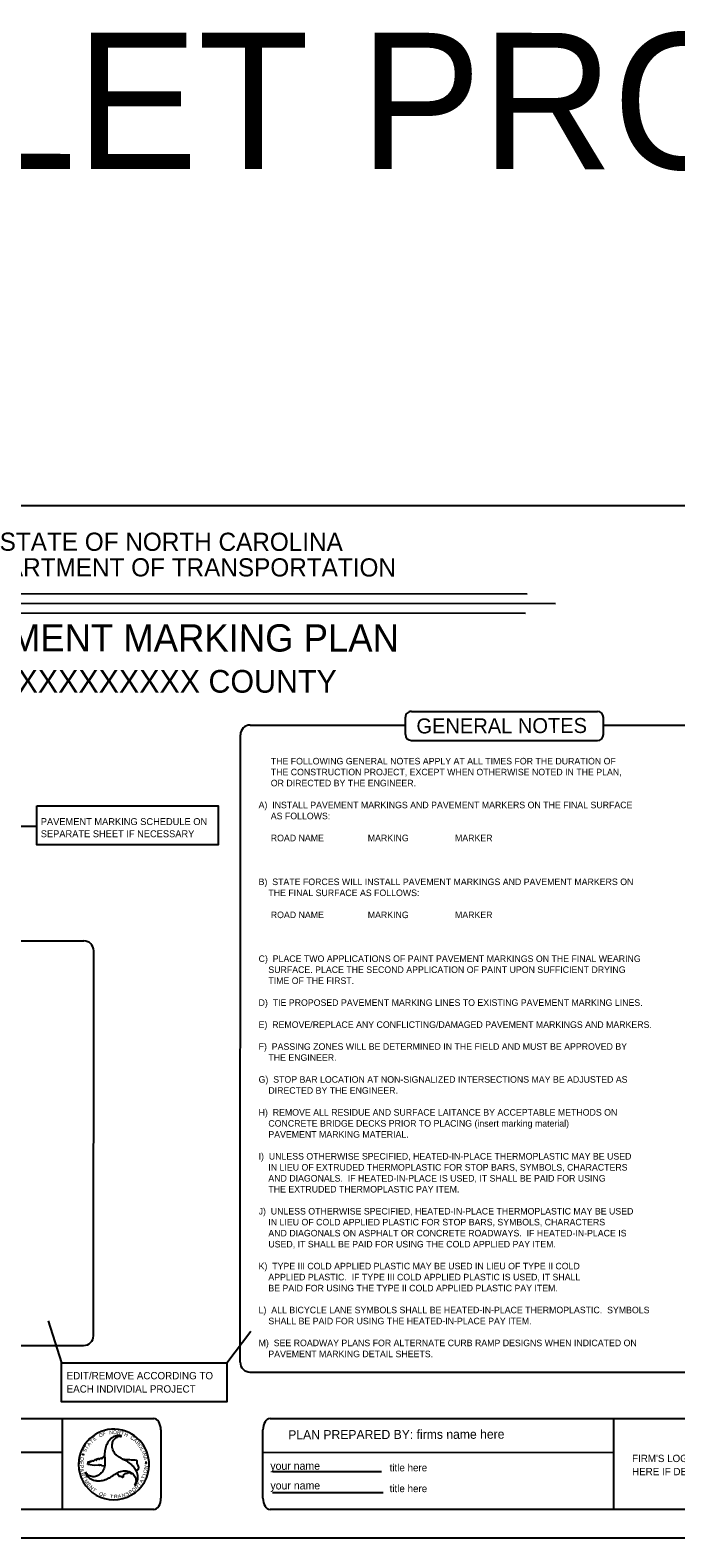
# Model space of a CAD drawing. Extents: x 2412958 to 2415566, y 564352 to 569392.
# Drawn here: x 2413907 to 2414563, y 567858 to 569392 of the extents above; entities that cross this region are included whole.
import ezdxf

# ---------------------------------------------------------------- set-up
doc = ezdxf.new("R2010")
doc.units = 0
for name, color, linetype in [('Default', 7, 'Continuous'), ('Sheet Title CELL', 7, 'Continuous'), ('Typical Detail Wedge1 CELL', 7, 'Continuous')]:
    doc.layers.add(name, color=color, linetype=linetype)

msp = doc.modelspace()

# ---------------------------------------------------------------- linework, layer by layer
at = {"layer": 'Default'}
for p, q in [((2413720.6, 568581.9), (2413913.3, 568581.9)), ((2413924.9, 568078.8), (2413938.3, 568036.1)), ((2414106.4, 568036.1), (2414130.9, 568068.2)), ((2413425.3, 567979.1), (2414032.2, 567979.2)), ((2413939.2, 567979.2), (2413939.2, 567886.8)), ((2414150.5, 567979.2), (2414647.4, 567979.2)), ((2414500.2, 567886.9), (2414500.2, 567979.2)), ((2414039.4, 567967.7), (2414039.5, 567898.4)), ((2414143.3, 567898.3), (2414143.3, 567967.7)), ((2413418.1, 567944.8), (2413939.2, 567945)), ((2414143.3, 567944.8), (2414500.2, 567945)), ((2414153.1, 567925.4), (2414263.8, 567925.4)), ((2414153.1, 567904.2), (2414265.6, 567904.2)), ((2414032.3, 567886.9), (2413425.3, 567886.8)), ((2414647.4, 567886.9), (2414150.5, 567886.8))]:
    msp.add_line(p, q, dxfattribs=at)
for points in [[(2413718.3, 568818.8), (2414412.1, 568818.4)], [(2413686.3, 568809), (2414440.8, 568808.7)], [(2413716.6, 568799.3), (2414410.4, 568798.9)]]:
    msp.add_lwpolyline(points, dxfattribs=at)
for points in [[(2413913.3, 568602.9), (2414097.7, 568602.9), (2414097.7, 568563.1), (2413913.3, 568563.1)], [(2413938.3, 568036.1), (2414106.4, 568036.1), (2414106.4, 567996.3), (2413938.3, 567996.3)]]:
    msp.add_lwpolyline(points, close=True, dxfattribs=at)
for centre, major_axis, start_param, end_param in [((2414032.2, 567967.7), (0, 11.5), 4.713091, 6.283887), ((2414150.5, 567967.7), (0, 11.5), 0.000702, 1.571498), ((2414032.3, 567898.4), (0, -11.5), 0.000702, 1.571498), ((2414150.5, 567898.3), (0, -11.5), 4.713091, 6.283887)]:
    msp.add_ellipse(centre, major_axis=major_axis, ratio=0.62659, start_param=start_param, end_param=end_param, dxfattribs=at)
at = {"layer": 'Sheet Title CELL'}
for p, q in [((2414288.2, 568675.3), (2414288.2, 568692.9)), ((2414489.6, 568675.2), (2414489.6, 568692.8)), ((2414130.3, 568685), (2414288.2, 568684.9)), ((2414489.6, 568684.9), (2414651.4, 568684.8)), ((2414120.1, 568036.6), (2414120.3, 568675)), ((2413885.3, 568465.4), (2413961.1, 568465.3)), ((2413970.9, 568063.4), (2413971.1, 568455.3)), ((2413428, 568053.6), (2413960.9, 568053.6)), ((2414130.1, 568026.6), (2414651.2, 568026.4)), ((2413999.5, 567961.5), (2413999.4, 567961.4)), ((2413999.5, 567961.5), (2413999.4, 567961.4)), ((2413960, 567942.6), (2413959.6, 567943)), ((2413959.6, 567943), (2413960.2, 567943)), ((2413959.8, 567942), (2413960, 567942.6)), ((2413960.3, 567942.3), (2413959.8, 567942)), ((2413960.2, 567943), (2413960.5, 567943.5)), ((2413960.8, 567941.9), (2413960.3, 567942.3)), ((2413960.5, 567943.5), (2413960.6, 567942.9)), ((2413960.6, 567942.9), (2413961.2, 567942.8)), ((2413961.2, 567942.8), (2413960.7, 567942.5)), ((2413960.7, 567942.5), (2413960.8, 567941.9)), ((2413965, 567932.6), (2413965.4, 567934.8)), ((2413972, 567931.4), (2413965, 567932.6)), ((2413976.2, 567932), (2413972, 567931.4)), ((2413982.2, 567930.7), (2413979.2, 567931.2)), ((2414000.4, 567938.2), (2414000.4, 567938.2)), ((2414024.2, 567934.7), (2414023.5, 567934.7)), ((2414023.5, 567934.7), (2414024, 567934.3)), ((2414024, 567934.3), (2414023.8, 567933.7)), ((2414023.8, 567933.7), (2414024.3, 567934)), ((2414024.5, 567935.2), (2414024.2, 567934.7)), ((2414024.3, 567934), (2414024.8, 567933.6)), ((2414024.6, 567934.6), (2414024.5, 567935.2)), ((2414025.2, 567934.5), (2414024.6, 567934.6)), ((2414024.7, 567934.2), (2414025.2, 567934.5)), ((2414024.8, 567933.6), (2414024.7, 567934.2)), ((2413997.4, 567919.9), (2413994.8, 567923.7)), ((2413994.8, 567923.7), (2413994.8, 567923.7))]:
    msp.add_line(p, q, dxfattribs=at)
msp.add_lwpolyline([(2414775.5, 568908), (2413275.5, 568907.9), (2413275.6, 567857.9), (2414775.6, 567858)], close=True, dxfattribs=at)
for points in [[(2414294.2, 568698.9), (2414483.6, 568698.8)], [(2414294.2, 568669.3), (2414483.6, 568669.2)]]:
    msp.add_lwpolyline(points, dxfattribs=at)
for centre, radius, start, end in [((2414294.2, 568692.9), 6, 89.9734, 179.9734), ((2414483.6, 568692.8), 6, 359.9734, 89.9734), ((2414130.3, 568675), 10, 89.9734, 179.9734), ((2414294.2, 568675.3), 6, 179.9734, 269.9734), ((2414483.6, 568675.2), 6, 269.9734, 359.9734), ((2413961.1, 568455.3), 10, 359.9734, 89.9734), ((2413960.9, 568063.6), 10, 269.9734, 359.9734), ((2414130.1, 568036.6), 10, 179.9734, 269.9734), ((2413991.6, 567932.6), 35.9, 352.4211, 172.4211), ((2414022.6, 568134.3), 197.4, 258.0996, 258.1992), ((2413991.6, 567932.6), 35.9, 172.4211, 352.4211), ((2414022.6, 568134.3), 197.4, 263.5387, 267.7447)]:
    msp.add_arc(centre, radius, start, end, dxfattribs=at)
for points in [[(2413999.4, 567961.4), (2413998.6, 567961.7), (2413996.1, 567962), (2413993.5, 567961.5), (2413993.3, 567961.4), (2413991.9, 567960.9), (2413990.5, 567960.1), (2413988.2, 567958.5), (2413986.3, 567956.3), (2413985.6, 567955.4), (2413985, 567954.2), (2413983.8, 567951.7), (2413983, 567949.3), (2413982.5, 567946.3), (2413982.2, 567943.7), (2413982.2, 567941), (2413982.4, 567938.3), (2413982.4, 567935.6), (2413982.4, 567932.9), (2413982.1, 567930.3), (2413982, 567930), (2413981.2, 567927.3), (2413979.7, 567924.9), (2413977.9, 567923.1), (2413976.9, 567922.2), (2413975.6, 567921.4), (2413974.8, 567920.9), (2413973, 567920.3), (2413970.4, 567920.1), (2413967.9, 567920.5), (2413965.8, 567921.4), (2413964, 567922.9), (2413962.7, 567924.9)], [(2414012.7, 567911.4), (2414013.4, 567911.9), (2414014.8, 567913.9), (2414015.7, 567916.4), (2414015.8, 567916.7), (2414016, 567918.1), (2414016.1, 567919.8), (2414015.8, 567922.6), (2414014.8, 567925.2), (2414014.4, 567926.3), (2414013.7, 567927.5), (2414012.1, 567929.7), (2414010.4, 567931.6), (2414008.1, 567933.6), (2414006, 567935.1), (2414003.6, 567936.5), (2414001.2, 567937.7), (2413998.9, 567939), (2413996.5, 567940.4), (2413994.4, 567942), (2413994.2, 567942.1), (2413992.2, 567944.3), (2413991, 567946.7), (2413990.2, 567949.2), (2413990, 567950.4), (2413990, 567952), (2413990, 567952.9), (2413990.3, 567954.8), (2413991.4, 567957.2), (2413993, 567959.1), (2413994.9, 567960.5), (2413997.1, 567961.3), (2413999.4, 567961.4), (2413999.5, 567961.5)], [(2413965.4, 567934.8), (2413965.3, 567935), (2413965.7, 567935.2), (2413966.7, 567934.7), (2413967.3, 567935), (2413967.3, 567935.5), (2413967.8, 567935.9), (2413968.5, 567935.6), (2413969.3, 567936.4), (2413969.9, 567936.4), (2413971.1, 567936.3), (2413972.8, 567937.6), (2413973.5, 567937.6), (2413973.6, 567937.2), (2413973.9, 567937), (2413974.7, 567938.2), (2413974.9, 567938.3), (2413976.2, 567938.6), (2413976.4, 567938.4), (2413976.5, 567937.8), (2413976.6, 567937.7), (2413977, 567937.9), (2413977.6, 567938.5), (2413978.7, 567938.9), (2413979.7, 567938.6), (2413980, 567939.5), (2413981.4, 567940.2), (2413981.8, 567940.6), (2413981.9, 567941.2)], [(2413982.2, 567941.1), (2413982.2, 567941), (2413982.4, 567938.3), (2413982.4, 567935.6), (2413982.4, 567932.9), (2413982.2, 567930.7)], [(2413962.7, 567924.9), (2413962.9, 567924), (2413963.9, 567921.7), (2413965.6, 567919.7), (2413965.8, 567919.6), (2413966.9, 567918.6), (2413968.3, 567917.8), (2413970.9, 567916.6), (2413973.7, 567916.1), (2413974.8, 567915.9), (2413976.2, 567915.9), (2413978.9, 567916.2), (2413981.4, 567916.7), (2413984.3, 567917.7), (2413986.6, 567918.8), (2413989, 567920.2), (2413991.3, 567921.7), (2413993.6, 567923), (2413995.9, 567924.4), (2413998.4, 567925.4), (2413998.7, 567925.5), (2414001.5, 567926.1), (2414004.2, 567926), (2414006.7, 567925.5), (2414007.9, 567925), (2414009.3, 567924.2), (2414010.1, 567923.8), (2414011.5, 567922.5), (2414013.1, 567920.4), (2414013.9, 567918.1), (2414014.2, 567915.8), (2414013.8, 567913.5), (2414012.7, 567911.4)], [(2413979.2, 567931.2), (2413979, 567931.7), (2413978.5, 567932), (2413977.7, 567931.7), (2413977.1, 567931.8), (2413976.5, 567932.3), (2413976.2, 567932)], [(2413994.8, 567923.7), (2413995.9, 567924.4), (2413998.4, 567925.4), (2413998.7, 567925.5), (2414001.5, 567926.1), (2414004.2, 567926), (2414006.7, 567925.5), (2414007.9, 567925), (2414009.3, 567924.2), (2414010.1, 567923.8)], [(2414010.1, 567923.8), (2414009.6, 567923.2), (2414009.1, 567923.2), (2414008.2, 567924.1), (2414007, 567924.1), (2414006.4, 567924.5), (2414006.1, 567924.5), (2414005.1, 567923.5), (2414003.8, 567923.4), (2414001.7, 567922.3), (2414001.2, 567921.5), (2414001.1, 567919.7), (2414000.6, 567919.4), (2414000, 567919.6), (2413998.9, 567920.2), (2413997.4, 567919.9)], [(2414014.2, 567926.8), (2414013.7, 567927.5), (2414012.1, 567929.7), (2414010.4, 567931.6), (2414008.1, 567933.6), (2414006, 567935.1), (2414003.6, 567936.5), (2414001.2, 567937.7), (2414000.4, 567938.2)], [(2414014.8, 567937.1), (2414015, 567934.5), (2414016, 567931.4), (2414016.6, 567929.7), (2414016.4, 567928.3), (2414015.8, 567926.7), (2414014.2, 567926.8)]]:
    msp.add_spline(points, degree=3, dxfattribs=at)

# ---------------------------------------------------------------- texts
at = {"layer": 'Default'}
for s, height, rotation, p in [('FOR 2018 LET PROJECTS', 138.702, 359.9734, (2412942.9, 569251.3)), ('STATE OF NORTH CAROLINA', 18.494, 359.9734, (2413875.5, 568862.3)), ('DEPARTMENT OF TRANSPORTATION', 18.494, 359.9734, (2413832, 568836.3)), ('PAVEMENT MARKING PLAN', 27.74, 359.9734, (2413786.9, 568759.9)), ('XXXXXXXXXX COUNTY', 23.116, 359.9734, (2413873.1, 568718)), ('GENERAL NOTES', 15.257, 0.1557, (2414299.4, 568676.4)), ('            THE FOLLOWING GENERAL NOTES APPLY AT ALL TIMES FOR THE DURATION OF', 6.671, 360, (2414121.5, 568644.9)), ('            THE CONSTRUCTION PROJECT, EXCEPT WHEN OTHERWISE NOTED IN THE PLAN,', 6.671, 360, (2414121.5, 568633.8)), ('            OR DIRECTED BY THE ENGINEER.', 6.671, 360, (2414121.5, 568622.6)), ('       A)  INSTALL PAVEMENT MARKINGS AND PAVEMENT MARKERS ON THE FINAL SURFACE', 6.671, 360, (2414121.5, 568600.3)), ('PAVEMENT MARKING SCHEDULE ON', 7.053, 360, (2413917.3, 568583.2)), ('            AS FOLLOWS:', 6.671, 360, (2414121.5, 568589.1)), ('SEPARATE SHEET IF NECESSARY', 7.053, 360, (2413917.3, 568570.8)), ('            ROAD NAME                  MARKING                   MARKER            ', 6.671, 360, (2414121.5, 568566.7)), ('       B)  STATE FORCES WILL INSTALL PAVEMENT MARKINGS AND PAVEMENT MARKERS ON', 6.671, 360, (2414121.5, 568522.1)), ('           THE FINAL SURFACE AS FOLLOWS:', 6.671, 360, (2414121.5, 568510.9)), ('            ROAD NAME                  MARKING                   MARKER           ', 6.671, 360, (2414121.5, 568488.5)), ('       C)  PLACE TWO APPLICATIONS OF PAINT PAVEMENT MARKINGS ON THE FINAL WEARING', 6.671, 360, (2414121.5, 568443.9)), ('           SURFACE. PLACE THE SECOND APPLICATION OF PAINT UPON SUFFICIENT DRYING', 6.671, 360, (2414121.5, 568432.7)), ('           TIME OF THE FIRST.', 6.671, 360, (2414121.5, 568421.5)), ('       D)  TIE PROPOSED PAVEMENT MARKING LINES TO EXISTING PAVEMENT MARKING LINES.', 6.671, 360, (2414121.5, 568399.2)), ('       E)  REMOVE/REPLACE ANY CONFLICTING/DAMAGED PAVEMENT MARKINGS AND MARKERS.', 6.671, 360, (2414121.5, 568376.8)), ('       F)  PASSING ZONES WILL BE DETERMINED IN THE FIELD AND MUST BE APPROVED BY', 6.671, 360, (2414121.5, 568354.5)), ('           THE ENGINEER.', 6.671, 360, (2414121.5, 568343.3)), ('       G)  STOP BAR LOCATION AT NON-SIGNALIZED INTERSECTIONS MAY BE ADJUSTED AS ', 6.671, 360, (2414121.5, 568321)), ('           DIRECTED BY THE ENGINEER.', 6.671, 360, (2414121.5, 568309.8)), ('       H)  REMOVE ALL RESIDUE AND SURFACE LAITANCE BY ACCEPTABLE METHODS ON ', 6.671, 360, (2414121.5, 568287.5)), ('           CONCRETE BRIDGE DECKS PRIOR TO PLACING (insert marking material)  ', 6.671, 360, (2414121.5, 568276.3)), ('           PAVEMENT MARKING MATERIAL.', 6.671, 360, (2414121.5, 568265.1)), ('       I)  UNLESS OTHERWISE SPECIFIED, HEATED-IN-PLACE THERMOPLASTIC MAY BE USED', 6.671, 360, (2414121.5, 568242.8)), ('           IN LIEU OF EXTRUDED THERMOPLASTIC FOR STOP BARS, SYMBOLS, CHARACTERS ', 6.671, 360, (2414121.5, 568231.6)), ('           AND DIAGONALS.  IF HEATED-IN-PLACE IS USED, IT SHALL BE PAID FOR USING ', 6.671, 360, (2414121.5, 568220.4)), ('           THE EXTRUDED THERMOPLASTIC PAY ITEM.', 6.671, 360, (2414121.5, 568209.3)), ('       J)  UNLESS OTHERWISE SPECIFIED, HEATED-IN-PLACE THERMOPLASTIC MAY BE USED', 6.671, 360, (2414121.5, 568186.9)), ('           AND DIAGONALS ON ASPHALT OR CONCRETE ROADWAYS.  IF HEATED-IN-PLACE IS', 6.671, 360, (2414121.5, 568164.6)), ('           IN LIEU OF COLD APPLIED PLASTIC FOR STOP BARS, SYMBOLS, CHARACTERS ', 6.671, 360, (2414121.5, 568175.8)), ('           USED, IT SHALL BE PAID FOR USING THE COLD APPLIED PAY ITEM.', 6.671, 360, (2414121.5, 568153.4)), ('       K)  TYPE III COLD APPLIED PLASTIC MAY BE USED IN LIEU OF TYPE II COLD ', 6.671, 360, (2414121.5, 568131.1)), ('           APPLIED PLASTIC.  IF TYPE III COLD APPLIED PLASTIC IS USED, IT SHALL', 6.671, 360, (2414121.5, 568119.9)), ('           BE PAID FOR USING THE TYPE II COLD APPLIED PLASTIC PAY ITEM.', 6.671, 360, (2414121.5, 568108.7)), ('       L)  ALL BICYCLE LANE SYMBOLS SHALL BE HEATED-IN-PLACE THERMOPLASTIC.  SYMBOLS', 6.671, 360, (2414121.5, 568086.4)), ('           SHALL BE PAID FOR USING THE HEATED-IN-PLACE PAY ITEM.', 6.671, 360, (2414121.5, 568075.2)), ('       M)  SEE ROADWAY PLANS FOR ALTERNATE CURB RAMP DESIGNS WHEN INDICATED ON ', 6.671, 360, (2414121.5, 568052.9)), ('           PAVEMENT MARKING DETAIL SHEETS.', 6.671, 360, (2414121.5, 568041.7)), ('PLAN PREPARED BY: firms name here', 9.247, 0.1557, (2414169, 567958.2)), ('your name', 8, 0.1557, (2414150.8, 567927.1)), ('title here', 7.45, 359.9734, (2414272.1, 567925.6)), ('your name', 8, 0.1557, (2414150.9, 567907.1)), ('title here', 7.45, 359.9734, (2414272.1, 567904.4))]:
    msp.add_text(s, height=height, rotation=rotation, dxfattribs=at).set_placement(p)
at = {"layer": 'Sheet Title CELL'}
for s, height, rotation, p in [('A', 3.75, 50.7489, (2413966.6, 567950.8)), ('T', 3.72, 43.6937, (2413969.1, 567953.8)), ('E', 3.72, 36.5781, (2413971.7, 567956.3)), ('O', 3.74, 24.6387, (2413977.2, 567960)), ('F', 3.74, 17.4918, (2413980.8, 567961.6)), ('N', 3.73, 5.4049, (2413987.1, 567963.2)), ('O', 3.74, 357.9068, (2413990.7, 567963.5)), ('R', 3.73, 351.2969, (2413994.7, 567963.4)), ('T', 3.74, 344.6472, (2413998.2, 567962.8)), ('H', 3.73, 337.5625, (2414001.7, 567961.8)), ('C', 3.72, 325.2202, (2414007.9, 567959)), ('A', 3.73, 317.7231, (2414010.9, 567956.8)), ('R', 3.73, 311.3592, (2414013.7, 567954.2)), ('D', 3.73, 260.2741, (2413957.8, 567940.3)), ('S', 3.73, 64.1774, (2413963.1, 567944.5)), ('T', 3.74, 57.8012, (2413964.6, 567947.7)), ('O', 3.74, 304.2396, (2414016.1, 567951.6)), ('L', 3.72, 298.0059, (2414018.3, 567948.3)), ('I', 3.74, 294.0166, (2414019.8, 567945.4)), ('N', 3.73, 288.3165, (2414020.5, 567943.7)), ('A', 3.73, 280.8845, (2414021.6, 567940.2)), ('E', 3.72, 266.562, (2413957.1, 567936.1)), ('P', 3.73, 274.0944, (2413957, 567932)), ('A', 3.73, 280.687, (2413957.2, 567928)), ('R', 3.73, 287.7556, (2413958.1, 567923.7)), ('O', 3.72, 77.3812, (2414025.1, 567923.3)), ('N', 3.73, 84.6293, (2414026, 567927.7)), ('T', 3.73, 294.4062, (2413959.4, 567919.8)), ('M', 3.72, 301.6412, (2413961.2, 567916)), ('E', 3.72, 309.108, (2413963.8, 567912)), ('N', 3.74, 316.0795, (2413966.3, 567908.9)), ('T', 3.73, 322.9215, (2413969.4, 567906)), ('O', 3.74, 38.1354, (2414011.5, 567904.2)), ('R', 3.74, 45.3245, (2414015, 567907)), ('T', 3.72, 51.4242, (2414017.9, 567910)), ('A', 3.74, 59.5113, (2414020.5, 567913.3)), ('T', 3.73, 66.5957, (2414022.7, 567917.1)), ('I', 3.74, 72.2456, (2414024.3, 567921)), ('O', 3.73, 336.2252, (2413976.1, 567901.6)), ('F', 3.73, 343.3904, (2413980.2, 567899.8)), ('T', 3.72, 356.2997, (2413987.7, 567898.1)), ('R', 3.74, 3.2563, (2413991.9, 567897.9)), ('A', 3.72, 10.0094, (2413996, 567898.2)), ('N', 3.72, 17.041, (2414000.3, 567899)), ('S', 3.72, 24.2515, (2414004.4, 567900.3)), ('P', 3.73, 31.4434, (2414008.1, 567902.1))]:
    msp.add_text(s, height=height, rotation=rotation, dxfattribs=at).set_placement(p)
at = {"layer": 'Typical Detail Wedge1 CELL'}
for s, p in [('EDIT/REMOVE ACCORDING TO  ', (2413943.6, 568019.2)), ('EACH INDIVIDIAL PROJECT', (2413943.6, 568005.7)), ("FIRM'S LOGO OR NAME ", (2414518.7, 567935)), ('HERE IF DESIRED', (2414518.7, 567921.6))]:
    msp.add_text(s, height=7.45, dxfattribs=at).set_placement(p)

doc.saveas('drawing.dxf')
